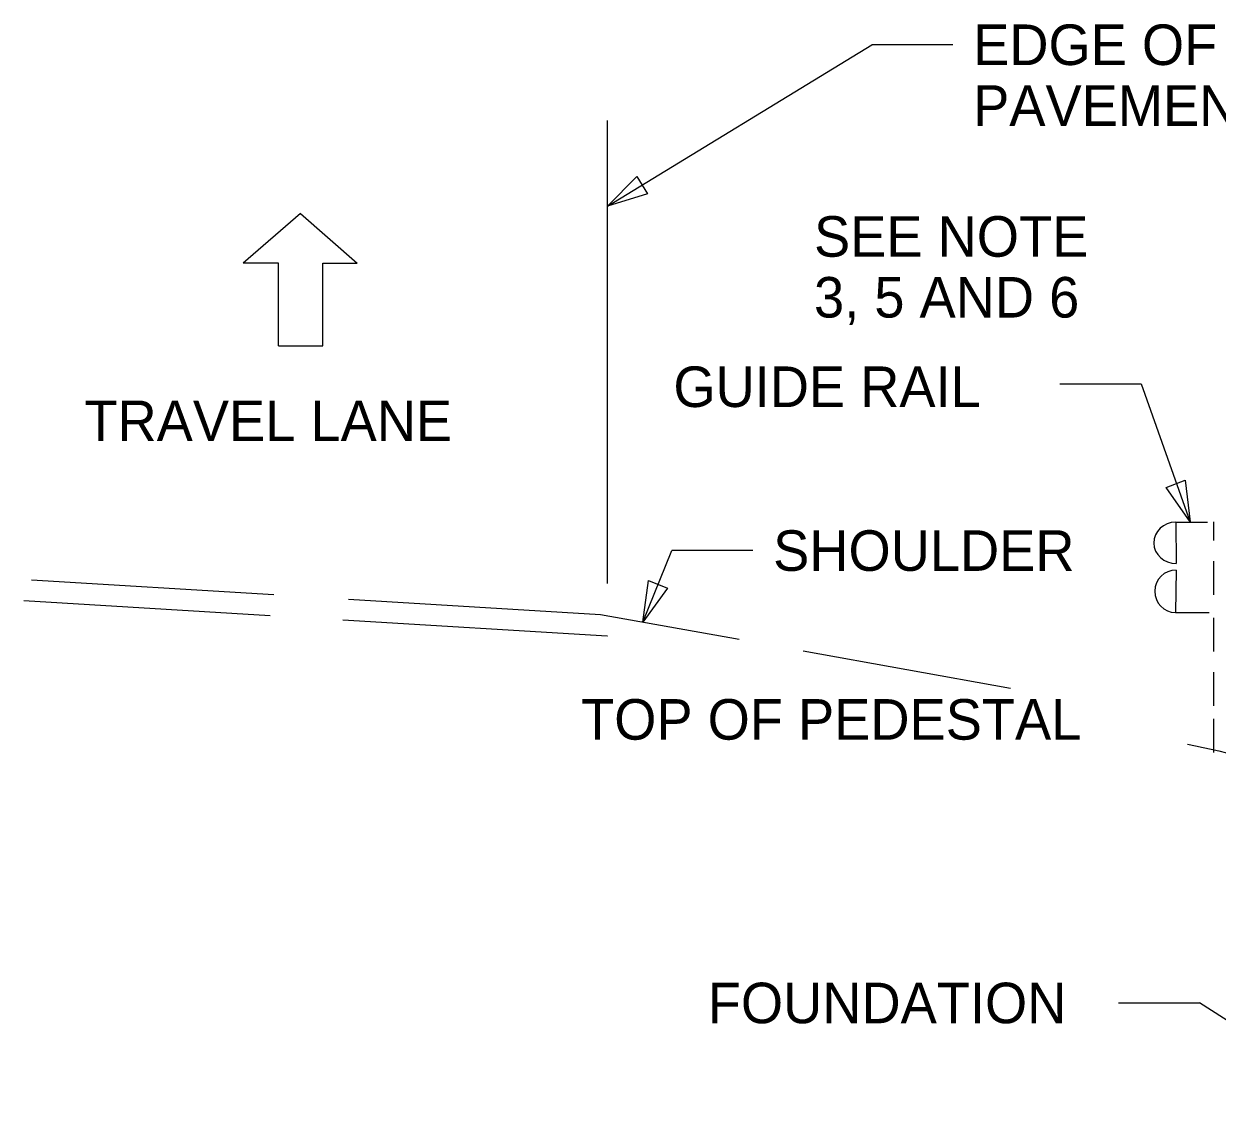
# Model space of a CAD drawing. Extents: x 1299104.8 to 1299141.6, y 239639.8 to 239661.8.
# Drawn here: x 1299122.193 to 1299125.724, y 239643.351 to 239646.58 of the extents above; entities that cross this region are included whole.
import ezdxf

# ---------------------------------------------------------------- set-up
doc = ezdxf.new("R2010")
doc.units = 0
for name, color, linetype in [('DIM TXT', 7, 'Continuous'), ('Level 3', 7, 'Continuous'), ('Level 8', 7, 'Continuous')]:
    doc.layers.add(name, color=color, linetype=linetype)

msp = doc.modelspace()

# ---------------------------------------------------------------- linework, layer by layer
at = {"layer": 'Level 3'}
for p, q in [((1299123.0120227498, 239646.0190778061), (1299122.8419379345, 239645.87154762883)), ((1299123.0120227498, 239646.0190778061), (1299123.1796928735, 239645.87154762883)), ((1299122.9466751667, 239645.87154762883), (1299122.8419379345, 239645.87154762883)), ((1299122.946675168, 239645.6267145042), (1299122.9466751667, 239645.87154762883)), ((1299123.0773703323, 239645.6267145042), (1299123.0773703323, 239645.87154762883)), ((1299123.0773703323, 239645.87154762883), (1299123.1796928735, 239645.87154762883)), ((1299122.946675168, 239645.6267145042), (1299123.0773703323, 239645.6267145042)), ((1299125.6013116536, 239645.1057998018), (1299125.6950351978, 239645.1057998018)), ((1299125.6013116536, 239645.1057998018), (1299125.6029559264, 239644.98330148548)), ((1299125.7131221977, 239645.10662193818), (1299125.7131221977, 239645.05153880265)), ((1299125.7131221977, 239644.9898785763), (1299125.7131221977, 239644.89040007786)), ((1299125.7131221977, 239644.8221627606), (1299125.7131221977, 239644.72268426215)), ((1299125.7131221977, 239644.66184617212), (1299125.7131221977, 239644.56236767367)), ((1299125.7131221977, 239644.52308077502), (1299125.7131221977, 239644.42360227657))]:
    msp.add_line(p, q, dxfattribs=at)
for points in [[(1299125.6021337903, 239644.96357021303), (1299125.6004895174, 239644.83778335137), (1299125.699968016, 239644.83778335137)], [(1299122.215659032, 239644.93507615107), (1299122.9325158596, 239644.8914322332)], [(1299122.1932175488, 239644.87397518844), (1299122.9218852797, 239644.8296121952)], [(1299123.1537964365, 239644.87796015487), (1299123.899185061, 239644.8325791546), (1299124.3092234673, 239644.7588528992)], [(1299123.136769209, 239644.81652955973), (1299123.9188902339, 239644.7689122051), (1299123.9203994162, 239644.76864084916)], [(1299124.4985593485, 239644.72480968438), (1299125.1120286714, 239644.6145058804)]]:
    msp.add_lwpolyline(points, dxfattribs=at)
for centre, major_axis, ratio, start_param, end_param in [((1299125.6021337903, 239645.04455064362), (0.06595555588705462, 0.0008853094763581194), 0.9286428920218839, 1.5707963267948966, 4.71238898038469), ((1299125.6013116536, 239644.90067678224), (0.0008221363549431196, 0.06289343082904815), 0.9838272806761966, 0, 3.141592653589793)]:
    msp.add_ellipse(centre, major_axis=major_axis, ratio=ratio, start_param=start_param, end_param=end_param, dxfattribs=at)
msp.add_spline([(1299125.636235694, 239644.44863672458), (1299126.0058871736, 239644.34003340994), (1299126.0058592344, 239644.34003340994)], degree=3, dxfattribs=at)
at = {"layer": 'Level 8'}
for p, q in [((1299123.9201739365, 239646.04045708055), (1299124.7018672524, 239646.5180738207)), ((1299124.9418672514, 239646.5180738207), (1299124.7018672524, 239646.5180738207)), ((1299123.9203994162, 239644.92412419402), (1299123.9203994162, 239646.29404726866)), ((1299124.0245685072, 239644.81003479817), (1299124.110128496, 239645.0213489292)), ((1299124.3501284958, 239645.0213489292), (1299124.110128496, 239645.0213489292)), ((1299125.4314434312, 239643.68279786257), (1299125.6714434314, 239643.68279786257)), ((1299126.193359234, 239643.35091836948), (1299125.6714434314, 239643.68279786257))]:
    msp.add_line(p, q, dxfattribs=at)
for points in [[(1299124.0382141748, 239646.07742331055), (1299123.9201739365, 239646.04045708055), (1299124.0069312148, 239646.12862268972)], [(1299125.629206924, 239645.2293154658), (1299125.644341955, 239645.10655174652), (1299125.5732163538, 239645.20775030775)], [(1299124.097411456, 239644.91000431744), (1299124.0245685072, 239644.81003479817), (1299124.041797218, 239644.93252223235)]]:
    msp.add_lwpolyline(points, close=True, dxfattribs=at)
msp.add_lwpolyline([(1299125.2586410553, 239645.51450262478), (1299125.4986410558, 239645.51450262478), (1299125.644020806, 239645.1057998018)], dxfattribs=at)

# ---------------------------------------------------------------- texts
at = {"layer": 'DIM TXT'}
for s, height, p in [('EDGE OF ', 0.12000000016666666, (1299125.0018672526, 239646.45807382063)), ('PAVEMENT', 0.12000000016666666, (1299125.0018672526, 239646.27807382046)), ('SEE NOTE', 0.12000000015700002, (1299124.5310500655, 239645.8908511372)), ('3, 5 AND 6', 0.12000000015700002, (1299124.5310500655, 239645.71085113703)), ('GUIDE RAIL', 0.12000000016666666, (1299124.1149430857, 239645.44617378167)), ('TRAVEL LANE', 0.12000000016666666, (1299122.3722532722, 239645.34512978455)), ('SHOULDER', 0.12000000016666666, (1299124.4101284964, 239644.96134892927)), ('TOP OF PEDESTAL', 0.12000000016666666, (1299123.8418430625, 239644.46186397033)), ('FOUNDATION', 0.12000000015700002, (1299124.216794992, 239643.62279786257))]:
    msp.add_text(s, height=height, dxfattribs=at).set_placement(p)

doc.saveas('drawing.dxf')
